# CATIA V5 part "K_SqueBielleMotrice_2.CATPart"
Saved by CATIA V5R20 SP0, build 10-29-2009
Part number: Squelette_bielle_motrice_2
Publications: "Plan_bielle_motrice", "Axe_pivot_bielle_motrice_1'", "Axe_pivot_bielle_motrice_2'", "Droite_bielle_motrice_2"
Bounding box of the stored display mesh (mm): x -178.986 to -89.007, y -117.303 to -77.303, z -50.68 to -48.706
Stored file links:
  G:\Khaled_CFAO_2011\ST2M\ST2M_GR2\jcoetard\Khaled\CAD_CATIA\K_SqueBielleMotrice_2.CATPart
  G:\Khaled_CFAO_2011\ST2M\ST2M_GR2\jcoetard\jcoetard\Maquette_jcoetard\Squelette_bielle.CATPart
  G:\Khaled_CFAO_2011\ST2M\ST2M_GR2\jcoetard\Khaled\CAD_CATIA\K_Squelette.CATProduct
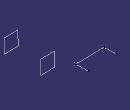
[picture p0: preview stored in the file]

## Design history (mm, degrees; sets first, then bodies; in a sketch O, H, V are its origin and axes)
Set1
  Point1 "Point.11": linked copy from another document
  Point2 "Point.12": linked copy from another document
  Plane1 "Plan_Ref": linked copy from another document
Set2 "Set géométrique"
  Plane2 "Plan_bielle_motrice": type Offset, RefPlane Plane1, Offset 117.303, reversed
  Line1 "Axe_pivot_bielle_motrice_1'": type Normal, RefPoint Point1, RefSkin Plane2, Start 0, End 40
  Line2 "Axe_pivot_bielle_motrice_2'": type Normal, RefPoint Point2, RefSkin Plane2, Start 0, End 40
  Line3 "Droite_bielle_motrice_2": type PtPt, FirstPoint Point2, SecondPoint Point1
Body1 (main body)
